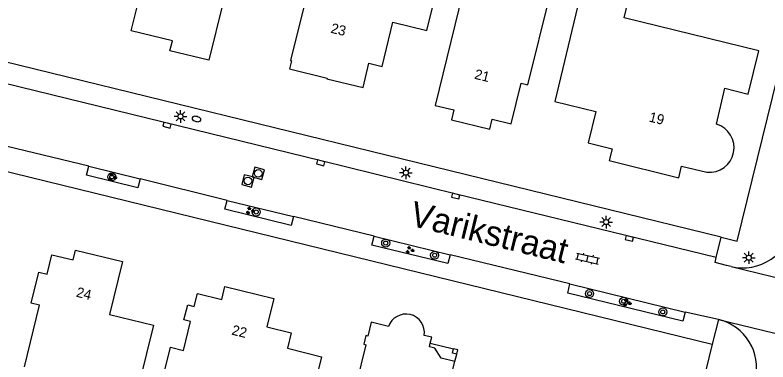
# Model space of a CAD drawing. Extents: x 125000 to 129004, y 397500 to 399008.
# Drawn here: x 126297.6 to 126372.5, y 398517.6 to 398552.1 of the extents above; entities that cross this region are included whole.
import ezdxf

# ---------------------------------------------------------------- set-up
doc = ezdxf.new("R2010")
doc.units = 0
for name, color, linetype in [('gg-anno-huisnummerreeks BGT', 7, 'Continuous'), ('gg-anno-openbare ruimte label', 7, 'Continuous'), ('gg-bbg-hoofdgebouw', 7, 'Continuous'), ('gg-bbg-onder overbouw', 7, 'Continuous'), ('gg-bbg-pand overbouw', 7, 'Continuous'), ('gg-bbg-pilaar onder overbouw', 7, 'Continuous'), ('gg-bbg-pilaar pand', 7, 'Continuous'), ('gg-knt-verharding', 7, 'Continuous'), ('gg-knt-verharding nz', 7, 'Continuous'), ('gt-grn-weggrens', 7, 'Continuous'), ('gt-symb-boom', 7, 'Continuous'), ('gt-symb-brandkraan', 7, 'Continuous'), ('gt-symb-groenvak', 7, 'Continuous'), ('gt-symb-klinker verharding', 7, 'Continuous'), ('gt-symb-kolk', 7, 'Continuous'), ('gt-symb-lichtmast', 7, 'Continuous'), ('gt-symb-rioolschacht', 7, 'Continuous')]:
    doc.layers.add(name, color=color, linetype=linetype)

# ---------------------------------------------------------------- blocks, each defined once
blk = doc.blocks.new('gt0-KOLK')
at = {"layer": 'gt-symb-kolk'}
blk.add_lwpolyline([(0, 0), (0.375, 0), (0.375, 0.4), (-0.375, 0.4), (-0.375, 0), (0, 0)], dxfattribs=at)
blk = doc.blocks.new('gt0-BOOM')
at = {"layer": 'gt-symb-boom'}
for radius in [0.4, 0.2]:
    blk.add_circle((0, 0), radius, dxfattribs=at)
blk = doc.blocks.new('gt0-LMAST')
at = {"layer": 'gt-symb-lichtmast'}
for p, q in [((-0.182, 0.173), (-0.447, 0.438)), ((-0.005, 0.246), (-0.005, 0.621)), ((0.172, 0.173), (0.437, 0.438)), ((-0.255, -0.004), (-0.63, -0.004)), ((-0.182, -0.181), (-0.447, -0.446)), ((-0.005, -0.254), (-0.005, -0.629)), ((0.437, -0.446), (0.172, -0.181)), ((0.245, -0.004), (0.62, -0.004))]:
    blk.add_line(p, q, dxfattribs=at)
blk.add_circle((-0.005, -0.004), 0.25, dxfattribs=at)
blk = doc.blocks.new('gt0-GRVAK')
at = {"layer": 'gt-symb-groenvak'}
for p, q in [((-0.11, 0.189), (-0.228, 0.24)), ((-0.182, 0.153), (0.088, 0.153)), ((-0.091, 0.211), (-0.156, 0.322)), ((-0.047, 0.214), (-0.047, 0.393)), ((-0.004, 0.211), (0.061, 0.322)), ((0.015, 0.189), (0.133, 0.24)), ((0.262, -0.052), (0.197, 0.059)), ((0.305, -0.049), (0.305, 0.13)), ((0.349, -0.052), (0.414, 0.059)), ((-0.245, -0.228), (-0.363, -0.177)), ((-0.318, -0.264), (-0.047, -0.264)), ((-0.226, -0.206), (-0.291, -0.095)), ((-0.183, -0.203), (-0.183, -0.024)), ((-0.139, -0.206), (-0.074, -0.095)), ((-0.12, -0.228), (-0.002, -0.177)), ((0.243, -0.074), (0.125, -0.023)), ((0.17, -0.11), (0.441, -0.11)), ((0.368, -0.074), (0.486, -0.023))]:
    blk.add_line(p, q, dxfattribs=at)
blk = doc.blocks.new('gt0-BR')
at = {"layer": 'gt-symb-brandkraan'}
for centre, radius, start, end in [((-0.244, 0), 0.206, 107.56694, 252.43307), ((0.599, -2.664), 3, 106.89205, 107.56694), ((0, -0.691), 0.938, 73.10799, 106.89205), ((-0.599, -2.664), 3, 72.43309, 73.10799), ((0.244, 0), 0.206, 287.56695, 72.43309), ((0.599, 2.664), 3, 252.43307, 253.10797), ((0, 0.691), 0.938, 253.10797, 286.89206), ((-0.599, 2.664), 3, 286.89206, 287.56695)]:
    blk.add_arc(centre, radius, start, end, dxfattribs=at)
blk = doc.blocks.new('gt0-RS')
at = {"layer": 'gt-symb-rioolschacht'}
blk.add_lwpolyline([(-0.5, -0.5), (0.5, -0.5), (0.5, 0.5), (-0.5, 0.5)], close=True, dxfattribs=at)
blk.add_circle((0, 0), 0.375, dxfattribs=at)
blk = doc.blocks.new('gt0-KL1')
at = {"layer": 'gt-symb-klinker verharding'}
for p, q in [((-1.15, 0.3), (1.15, 0.3)), ((-1, -0.3), (-1, 0.3)), ((-0.5, 0.3), (-0.5, 0.45)), ((0, -0.3), (0, 0.3)), ((0.5, 0.3), (0.5, 0.45)), ((1, -0.3), (1, 0.3)), ((-1.15, -0.3), (1.15, -0.3)), ((-0.5, -0.45), (-0.5, -0.3)), ((0.5, -0.45), (0.5, -0.3))]:
    blk.add_line(p, q, dxfattribs=at)

msp = doc.modelspace()

# ---------------------------------------------------------------- linework, layer by layer
at = {"layer": 'gg-bbg-hoofdgebouw'}
for points in [[(126308.616, 398556.233), (126308.955, 398557.602), (126309.052, 398557.578), (126310.349, 398562.81), (126316.338, 398561.325), (126316.077, 398560.261), (126319.757, 398559.355), (126318.988, 398556.233), (126319.522, 398556.103), (126318.825, 398553.252), (126318.295, 398553.414), (126316.872, 398547.625), (126313.003, 398548.573), (126313.241, 398549.545), (126309.147, 398550.559), (126310.441, 398555.781), (126308.616, 398556.233)], [(126325.013, 398547.597), (126325.081, 398547.58), (126324.882, 398546.765), (126328.631, 398545.85), (126328.614, 398545.782), (126332.217, 398544.902), (126332.81, 398547.324), (126334.118, 398547.003), (126335.197, 398551.411), (126338.578, 398550.582), (126340.552, 398558.641), (126336.551, 398559.621), (126336.535, 398559.554), (126332.544, 398560.531), (126331.849, 398557.66), (126331.781, 398557.677), (126331.013, 398554.505), (126327.004, 398555.475), (126326.7, 398554.162), (126326.632, 398554.178), (126325.013, 398547.597)], [(126367.396, 398541.262), (126368.227, 398544.862), (126370.547, 398544.258), (126371.602, 398548.58), (126358.196, 398551.852), (126359.151, 398555.768), (126354.906, 398556.804)], [(126342.108, 398554.27), (126339.385, 398543.128), (126341.258, 398542.677), (126341.022, 398541.705), (126344.84, 398540.778), (126345.074, 398541.75), (126346.962, 398541.295), (126347.951, 398545.337), (126348.629, 398545.171), (126350.832, 398554.179), (126348.081, 398554.852), (126347.61, 398552.924), (126342.108, 398554.27)], [(126353.976, 398554.629), (126351.294, 398543.508), (126355.395, 398542.519), (126354.612, 398539.416), (126356.999, 398538.814), (126356.71, 398537.649), (126363.646, 398535.933), (126363.918, 398537.093), (126366.434, 398536.49)], [(126298.509, 398517.095), (126300.001, 398523.224), (126299.186, 398523.427), (126299.955, 398526.521), (126300.773, 398526.326), (126301.233, 398528.262), (126303.371, 398527.754), (126303.61, 398528.725), (126308.275, 398527.574), (126306.986, 398522.322), (126311.364, 398521.248), (126309.32, 398512.919), (126304.622, 398514.072)], [(126313.044, 398519.053), (126314.344, 398518.739), (126315.034, 398521.607), (126314.39, 398521.762), (126314.763, 398523.256), (126315.403, 398523.097), (126315.727, 398524.397), (126318.148, 398523.793), (126318.465, 398525.095), (126323.329, 398523.911), (126322.65, 398521.072), (126325.061, 398520.47), (126324.697, 398518.946), (126328.087, 398518.082), (126325.609, 398507.954), (126320.549, 398509.187), (126321.285, 398512.208), (126313.233, 398514.171), (126313.399, 398514.851), (126312.097, 398515.168), (126313.044, 398519.053)], [(126334.757, 398521.11), (126333.036, 398521.534), (126332.698, 398520.153), (126332.479, 398520.202), (126332.296, 398519.34), (126332.501, 398519.297), (126330.568, 398511.45)], [(126338.91, 398519.441), (126339.058, 398520.042), (126338.301, 398520.228)], [(126344.278, 398514.866), (126344.47, 398515.646), (126341.069, 398516.469), (126341.346, 398517.633)]]:
    msp.add_lwpolyline(points, dxfattribs=at)
for centre, radius, start, end in [((126366.711, 398538.917), 2.443, 263.48498, 73.71973), ((126336.499, 398520.518), 1.84, 77.32824, 161.21981), ((126336.462, 398520.506), 1.86, 351.40483, 76.27916)]:
    msp.add_arc(centre, radius, start, end, dxfattribs=at)
at = {"layer": 'gg-bbg-onder overbouw'}
msp.add_lwpolyline([(126341.346, 398517.633), (126339.981, 398517.964), (126339.373, 398518.96), (126338.826, 398519.1), (126338.91, 398519.441)], dxfattribs=at)
at = {"layer": 'gg-bbg-pand overbouw'}
for p, q in [((126338.91, 398519.441), (126341.218, 398518.89)), ((126341.346, 398517.633), (126341.538, 398518.374))]:
    msp.add_line(p, q, dxfattribs=at)
at = {"layer": 'gg-bbg-pilaar onder overbouw'}
msp.add_lwpolyline([(126341.538, 398518.374), (126341.12, 398518.472), (126341.218, 398518.89)], dxfattribs=at)
at = {"layer": 'gg-bbg-pilaar pand'}
msp.add_lwpolyline([(126341.538, 398518.374), (126341.636, 398518.792), (126341.218, 398518.89)], dxfattribs=at)
at = {"layer": 'gg-knt-verharding'}
for p, q in [((126272.28, 398542.545), (126366.982, 398519.368)), ((126304.923, 398537.078), (126310.026, 398535.826)), ((126318.685, 398533.676), (126325.288, 398532.072)), ((126333.318, 398530.104), (126340.897, 398528.255)), ((126367.377, 398527.969), (126367.858, 398530.005)), ((126352.806, 398525.35), (126364.279, 398522.536)), ((126367.604, 398521.823), (126366.982, 398519.368)), ((126366.982, 398519.368), (126363.002, 398503.286))]:
    msp.add_line(p, q, dxfattribs=at)
for points in [[(126367.858, 398530.005), (126369.442, 398529.597), (126375.987, 398556.219)], [(126367.858, 398530.005), (126278.921, 398551.771), (126274.923, 398552.786)], [(126310.026, 398535.826), (126309.8, 398534.922), (126304.688, 398536.173), (126304.923, 398537.078)], [(126325.288, 398532.072), (126325.062, 398531.164), (126318.462, 398532.796), (126318.685, 398533.676)], [(126340.897, 398528.255), (126340.656, 398527.372), (126333.097, 398529.204), (126333.318, 398530.104)], [(126368.842, 398527.078), (126368.394, 398527.204), (126367.258, 398527.478), (126367.377, 398527.969)], [(126364.279, 398522.536), (126364.061, 398521.64), (126352.592, 398524.437), (126352.806, 398525.35)]]:
    msp.add_lwpolyline(points, dxfattribs=at)
for centre, radius, start, end in [((126369.988, 398532.032), 5.085, 256.97565, 350.80248), ((126366.424, 398517.009), 4.956, 346.85099, 76.224)]:
    msp.add_arc(centre, radius, start, end, dxfattribs=at)
at = {"layer": 'gg-knt-verharding nz'}
for p, q in [((126304.923, 398537.078), (126295.359, 398539.392)), ((126318.685, 398533.676), (126310.026, 398535.826)), ((126333.318, 398530.104), (126325.288, 398532.072)), ((126352.806, 398525.35), (126340.897, 398528.255)), ((126367.604, 398521.823), (126364.279, 398522.536))]:
    msp.add_line(p, q, dxfattribs=at)
msp.add_lwpolyline([(126367.377, 398527.969), (126341.482, 398534.298), (126328.05, 398537.605), (126280.582, 398549.244), (126274.413, 398550.735)], dxfattribs=at)
at = {"layer": 'gt-grn-weggrens'}
for p, q in [((126368.842, 398527.078), (126383.782, 398523.448)), ((126367.604, 398521.823), (126382.432, 398518.213))]:
    msp.add_line(p, q, dxfattribs=at)

# ---------------------------------------------------------------- block references
at = {"layer": 'gt-symb-boom'}
for p in [(126307.204, 398536.011), (126321.584, 398532.516), (126334.472, 398529.42), (126339.34, 398528.214), (126354.762, 398524.388), (126358.158, 398523.624), (126362.051, 398522.559)]:
    msp.add_blockref('gt0-BOOM', p, dxfattribs=at)
at = {"layer": 'gt-symb-brandkraan', "rotation": -13.8834180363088}
msp.add_blockref('gt0-BR', (126315.633, 398541.777), dxfattribs=at)
at = {"layer": 'gt-symb-groenvak'}
for p in [(126307.254, 398535.989), (126320.952, 398532.646), (126336.854, 398528.729), (126358.468, 398523.462)]:
    msp.add_blockref('gt0-GRVAK', p, dxfattribs=at)
at = {"layer": 'gt-symb-klinker verharding', "rotation": -12.827123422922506}
msp.add_blockref('gt0-KL1', (126354.564, 398527.881), dxfattribs=at)
at = {"layer": 'gt-symb-kolk'}
for p, rotation in [((126312.753, 398541.351), 166.2278545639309), ((126328.05, 398537.605), 166.22785456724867), ((126341.482, 398534.298), 166.17220496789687), ((126358.771, 398530.076), 166.28353067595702)]:
    msp.add_blockref('gt0-KOLK', p, dxfattribs=dict(at, rotation=rotation))
at = {"layer": 'gt-symb-lichtmast'}
for p in [(126314.053, 398542.04), (126336.487, 398536.43), (126356.419, 398531.514), (126370.612, 398527.968)]:
    msp.add_blockref('gt0-LMAST', p, dxfattribs=at)
at = {"layer": 'gt-symb-rioolschacht'}
for p, rotation in [((126321.788, 398536.358), 164.99108632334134), ((126320.761, 398535.605), -14.064036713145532)]:
    msp.add_blockref('gt0-RS', p, dxfattribs=dict(at, rotation=rotation))

# ---------------------------------------------------------------- texts
at = {"layer": 'gg-anno-huisnummerreeks BGT'}
for s, rotation, p in [('23', 346.4, (126328.935, 398550.378)), ('21', 346.4, (126343.241, 398545.796)), ('19', 346.1, (126360.61, 398541.538)), ('24', 346.1, (126303.598, 398524.094)), ('22', 346.3, (126319.073, 398520.316))]:
    msp.add_text(s, height=1, rotation=rotation, dxfattribs=at).set_placement(p)
at = {"layer": 'gg-anno-openbare ruimte label'}
for s, rotation, p in [('Varikstraat', 346.2, (126336.739, 398531.195)), ('Vierhoutenstraat', 75.3, (126370.302, 398497.06))]:
    msp.add_text(s, height=2.5, rotation=rotation, dxfattribs=at).set_placement(p)

doc.saveas('drawing.dxf')
